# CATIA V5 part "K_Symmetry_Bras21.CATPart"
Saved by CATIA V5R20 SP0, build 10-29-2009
Part number: Symmetry of Bras21
Bounding box of the stored display mesh (mm): x 4 to 44, y -5 to 5.003, z -91.99 to 4.99
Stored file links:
  G:\Khaled_CFAO_2011\SIL\SIL_GR2\zthiebault\Khaled\CAD_ThinkMOTION\K_Symmetry_Bras21.CATPart
  G:\Khaled_CFAO_2011\SIL\SIL_GR2\zthiebault\Khaled\CAD_ThinkMOTION\K_Bras21.CATPart
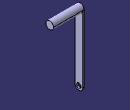
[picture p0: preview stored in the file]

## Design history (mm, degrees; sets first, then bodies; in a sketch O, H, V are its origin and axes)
Body1 (main body)
  Body2 "Corps du corps principal d'origine"
    Solid1: linked copy from another document
  Assemble1: tool Body2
